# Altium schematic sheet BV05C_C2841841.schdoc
size 127 x 101 mm
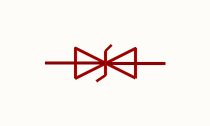
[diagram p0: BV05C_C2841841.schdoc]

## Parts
U?  bv05c_c2841841  [SOD-323_L1.8-W1.3-LS2.6-BI]  (value not drawn)

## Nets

Not connected (* = marked no-connect by the designer): U? 1 2

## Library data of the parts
U? = bv05c_c2841841: 极性:双向;反向截止电压(Vrwm):5V;钳位电压:9V；20V;峰值脉冲电流(Ipp):10A;击穿电压:8V;; Manufacturer: TECH PUBLIC(台舟); ManufacturerPart: BV05C; AddInBom: yes; ModelId: 0438885a1290498eba882c897197ad84; ModelTransform: 104.3305,51.181,0,0,0,0,0,0,0; Polarity: 双向; Reverse Stand-Off Voltage (Vrwm): 5V; Clamping Voltage: 9V；20V; Peak Pulse Current (Ipp): 10A; Voltage - Breakdown: 8V; Reverse Leakage Current (Ir): 200nA; Number of Channels: 单路; level of protection: IEC 61000-4-2；IEC 61000-4-4; Junction Capacitance: 1pF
